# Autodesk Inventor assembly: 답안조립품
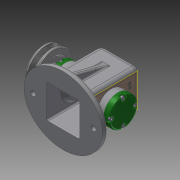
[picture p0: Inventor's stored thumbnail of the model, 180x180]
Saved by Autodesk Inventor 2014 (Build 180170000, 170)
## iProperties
Created: 2017-07
Part Number: 답안조립품
Document SubType Name: Weldment
Designer: 406-3333
Weld Material: Welded Aluminum-6061
Author: 406-3333
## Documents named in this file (10)
- C:\Users\406-3333\Desktop\470707V1013\답안조립품.iam
- C:\Users\406-3333\Desktop\470707V1013\편심축.ipt
- C:\Users\406-3333\Desktop\470707V1013\키 4 x 4 x 10.ipt
- C:\Users\406-3333\Desktop\470707V1013\베어링 12 x 32 x 10.ipt
- C:\Users\406-3333\Desktop\470707V1013\본체.ipt
- C:\Users\406-3333\Desktop\470707V1013\앞커버.ipt
- C:\Users\406-3333\Desktop\470707V1013\뒤커버.ipt
- C:\Users\406-3333\Desktop\470707V1013\볼트 M4 x 12.ipt
- C:\Users\406-3333\Desktop\470707V1013\V벨트풀리.ipt
- C:\Users\406-3333\Desktop\470707V1013\오일실 12 25 7.ipt
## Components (1 placed, 1 different names)
1. V벨트풀리:1 — 각도:3
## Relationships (1: Angle 1)
- 각도:3 [Angle]: V벨트풀리:1
